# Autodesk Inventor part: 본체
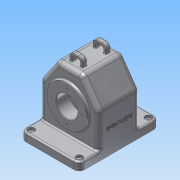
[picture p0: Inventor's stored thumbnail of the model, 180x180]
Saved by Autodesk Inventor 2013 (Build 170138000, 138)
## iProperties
Created: 2016-12
Part Number: 본체
Material: 알루미늄 6061
Document SubType Name: Modeling
Designer: Administrator
Density: 2.71 g/cm^3
Mass: 1063.78 g
Surface Area: 1146.71 cm^2
Volume: 392.539 cm^3
Author: Administrator
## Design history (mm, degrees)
sketch "스케치1"
  geometry: L1 (-65, 55)-(65, 55); L2 (75, 45)-(75, -45); L3 (65, -55)-(-65, -55); L4 (-75, -45)-(-75, 45); A1 r 10 centre (-65, 45) between (-65, 55) and (-75, 45); A2 r 10 centre (65, 45) between (75, 45) and (65, 55); A3 r 10 centre (-65, -45) between (-75, -45) and (-65, -55); A4 r 10 centre (65, -45) between (65, -55) and (75, -45); 6 further points
  constraints: 8 end point, 8 point on circle, 8 tangent, 6 point on line, 4 centre point, 3 equal radius, 2 midpoint, 2 parallel, 1 horizontal, 1 horizontal alignment, 1 perpendicular, 1 vertical alignment
  dimensions: "d0" = 150 distance of point (-75, 55) point (75, 55); "d2" = 110 distance of point (75, 55) point (75, -55); "d3" = 10 radius of A1
extrude "돌출1" new body sketch "스케치1" distance "d4" = 15; taper "d5" = 0 deg
sketch "스케치2"
  geometry: L1 (-55, 0)-(-55, 15) reference; L2 (-55, 15)-(55, 15) reference; L3 (55, 15)-(55, 0) reference; L4 (55, 0)-(-55, 0) reference; L5 (-55, 15)-(-55, 80); L6 (-23.491, 125)-(23.491, 125); L7 (55, 80)-(55, 15); L8 (-23.491, 125)-(-55, 80); L9 (23.491, 125)-(55, 80); 3 further points
  constraints: 10 end point, 2 midpoint, 2 perpendicular, 1 horizontal alignment, 1 point on line, 1 vertical, 1 vertical alignment
  dimensions: "d6" = 125 distance between parallel lines of L4 L6; "d7" = 80 distance from line of L7.start L4; "d24" = 35 deg angle of L5 L8; "d25" = 35 deg angle of L7 L9
extrude "돌출2" join sketch "스케치2" stored distance "d12" = 77; taper "d13" = 0 deg
sketch "스케치3"
  geometry: L1 (-15, -55)-(-15, 55) reference; L2 (-80, 55)-(-15, 55) reference; L3 (-15, -55)-(-80, -55) reference; L4 (0, -55)-(-15, -55) reference; L5 (0, 55)-(0, -55) reference; L6 (-15, 55)-(0, 55) reference; L7 (-125, -23.491)-(-125, 23.491) reference; L8 (-125, 23.491)-(-80, 55) reference; L9 (-80, -55)-(-125, -23.491) reference; C1 r 37.5 at (-65, 0); 2 further points
  constraints: 1 centre point, 1 horizontal alignment, 1 midpoint
  dimensions: "d15" = 65 distance from line of L5 C1.centre; "d16" = 75 diameter of C1
extrude "돌출3" join sketch "스케치3" distance "d17" = 5; taper "d18" = 0 deg
sketch "스케치4"
  geometry: L1 (15, 55)-(15, -55) reference; L2 (80, -55)-(15, -55) reference; L3 (15, 55)-(80, 55) reference; L4 (0, 55)-(15, 55) reference; L5 (0, -55)-(0, 55) reference; L6 (15, -55)-(0, -55) reference; L7 (125, 23.491)-(125, -23.491) reference; L8 (125, -23.491)-(80, -55) reference; L9 (80, 55)-(125, 23.491) reference; C1 r 31 at (65, 0); 2 further points
  constraints: 1 centre point, 1 horizontal alignment, 1 midpoint
  dimensions: "d19" = 62 diameter of C1; "d21" = 65 distance of point (0, 0) C1.centre
extrude "돌출4" join sketch "스케치4" distance "d22" = 10; taper "d23" = 0 deg
sketch "스케치6"
  geometry: L1 (-23.491, 125)-(23.491, 125) reference; L2 (23.491, 125)-(55, 80) reference; L3 (55, 80)-(55, 0) reference; L4 (55, 0)-(-55, 0) reference; L5 (-55, 0)-(-55, 80) reference; L6 (-55, 80)-(-23.491, 125) reference; L7 (50, 78.424)-(20.888, 120); L8 (20.888, 120)-(-20.888, 120); L9 (-20.888, 120)-(-50, 78.424); L10 (-50, 78.424)-(-50, 0); L11 (50, 0)-(50, 78.424); 1 further point
  constraints: 10 end point, 2 point on line, 2 other
  dimensions: "d26" = 5 distance between parallel lines of L1 L8; "d27" = 5 distance between parallel lines of L5 L10; "d28" = 5 distance between parallel lines of L11 L3
extrude "돌출5" cut sketch "스케치6" stored distance "d29" = 67; taper "d30" = 0 deg
sketch "스케치7"
  geometry: L1 (-33.5, 78.424)-(-33.5, 0) reference; L2 (-33.5, 120)-(-33.5, 78.424) reference; L3 (-43.5, 102.5)-(-43.5, 27.5) reference; L4 (33.5, 0)-(-33.5, 0) reference; L5 (-38.5, 65)-(-19.5, 65); L6 (-38.5, 111)-(-19.5, 92); L7 (-19.5, 92)-(-19.5, 65); L8 (-38.5, 125)-(-38.5, 80) reference; L9 (-38.5, 111)-(-38.5, 65); 2 further points
  constraints: 8 end point, 1 collinear, 1 horizontal alignment, 1 midpoint, 1 parallel, 1 perpendicular, 1 point on line
  dimensions: "d39" = 24 distance between parallel lines of L7 L3; "d40" = 54 diameter of L6.end L5; "d41" = 45 deg angle of L7 L6
revolve "회전1" sketch "스케치7" stored, may be unused: angle "d42" = 90 deg
hole "구멍1" diameter "d45" = 40; stored, may be unused: countersink angle "d49" = 90 deg, drill point angle "d51" = 0 deg; dims "d43" = 10, "d44" = 10, "d46" = 6, "d47" = 4, "d48" = 2, "d50" = 8
hole "구멍2" diameter "d54" = 5; stored, may be unused: countersink angle "d58" = 90 deg, drill point angle "d60" = 0 deg; dims "d52" = 10, "d53" = 10, "d55" = 6, "d56" = 12, "d57" = 5, "d59" = 8
hole "구멍3" diameter "d63" = 5; stored, may be unused: countersink angle "d67" = 90 deg, drill point angle "d69" = 0 deg; dims "d61" = 10, "d62" = 10, "d64" = 6, "d65" = 12, "d66" = 5, "d68" = 8
hole "구멍4" diameter "d72" = 5; stored, may be unused: countersink angle "d76" = 90 deg, drill point angle "d78" = 0 deg; dims "d70" = 10, "d71" = 10, "d73" = 6, "d74" = 12, "d75" = 5, "d77" = 8
hole "구멍5" diameter "d81" = 5; stored, may be unused: countersink angle "d85" = 90 deg, drill point angle "d87" = 0 deg; dims "d79" = 10, "d80" = 10, "d82" = 6, "d83" = 12, "d84" = 5, "d86" = 8
node "작업 평면1"
sketch "스케치9"
  geometry: L1 (103.5, -15)-(103.5, -80) reference; L2 (130, 0)-(0, 0) reference; 3 further points
  constraints: 1 coincident, 1 other
  dimensions: "d102" = 38.5 distance from line of point (65, -45) L1; "d103" = 45 distance from line of L2 point (65, -45)
feature "엠보싱1" sketch "스케치9" dims "d6" = 125, "d7" = 80, "d24" = 35 deg, "d25" = 35 deg, "d104" = 0.5, "d105" = 0
chamfer "모따기1" distance "d106" = 1; stored, may be unused: second distance "d107" = 2, angle "d108" = 45 deg
chamfer "모따기2" distance "d109" = 1; stored, may be unused: second distance "d110" = 2, angle "d111" = 45 deg
fillet "모깎기3" dims "d113" = 10
fillet "모깎기4" dims "d114" = 10
fillet "모깎기5" dims "d115" = 8
sketch "스케치10" dims "d116" = 52
  geometry: C1 r 31 at (0, 0) reference; 3 further points
  constraints: 2 horizontal alignment, 1 coincident, 2 other
hole "구멍6" sketch "스케치10" at (26, 0) diameter "d118" = 2.459; stored, may be unused: countersink angle "d122" = 90 deg, drill point angle "d124" = 118 deg; dims "d119" = 6, "d120" = 12, "d121" = 5, "d123" = 8
sketch "스케치11" dims "d128" = 58
  geometry: C1 r 27 at (0, 0) reference; C2 r 41 at (0, 0) reference; 3 further points
  constraints: 2 horizontal alignment, 1 coincident, 2 other
hole "구멍7" sketch "스케치11" at (-29, 0) diameter "d130" = 2.459; stored, may be unused: countersink angle "d134" = 90 deg, drill point angle "d136" = 118 deg; dims "d131" = 6, "d132" = 12, "d133" = 5, "d135" = 8
fillet "모깎기6" dims "d140" = 3
fillet "모깎기7" dims "d141" = 3
fillet "모깎기8" dims "d142" = 3
fillet "모깎기9" dims "d143" = 3
fillet "모깎기11" dims "d145" = 5
fillet "모깎기12" dims "d146" = 3
fillet "모깎기13" dims "d147" = 3
fillet "모깎기14" dims "d148" = 3
node "작업 평면2"
sketch "스케치12"
  geometry: L1 (-76.847, 55)-(0, 55) reference; L2 (0, 55)-(0, 50) reference; L3 (0, 50)-(-77.478, 50) reference; L4 (-79.198, 49.457)-(-117.868, 22.381) reference; L5 (-120, 18.285)-(-120, -18.285) reference; L6 (-117.868, -22.381)-(-79.198, -49.457) reference; L7 (-77.478, -50)-(0, -50) reference; L8 (0, -50)-(0, -55) reference; L9 (0, -55)-(-76.847, -55) reference; L10 (-82.583, -53.192)-(-120.736, -26.477) reference; L11 (-125, -18.285)-(-125, 18.285) reference; L12 (-120.736, 26.477)-(-82.583, 53.192) reference; L13 (-125, -12.5)-(-132, -12.5); L14 (-140, -4.5)-(-140, 4.5); L15 (-132, 12.5)-(-125, 12.5); L16 (0, 47)-(0, -47) reference; L17 (-125, 7.5)-(-132, 7.5); L18 (-135, 4.5)-(-135, -4.5); L19 (-132, -7.5)-(-125, -7.5); C1 r 33.5 at (-65, 0) reference; C2 r 20 at (-65, 0) reference; A1 r 3 centre (-77.478, 47) between (-77.478, 50) and (-79.198, 49.457) reference; A2 r 5 centre (-115, 18.285) between (-117.868, 22.381) and (-120, 18.285) reference; A3 r 5 centre (-115, -18.285) between (-120, -18.285) and (-117.868, -22.381) reference; A4 r 3 centre (-77.478, -47) between (-79.198, -49.457) and (-77.478, -50) reference; A5 r 10 centre (-76.847, -45) between (-82.583, -53.192) and (-76.847, -55) reference; A6 r 10 centre (-115, -18.285) between (-125, -18.285) and (-120.736, -26.477) reference; A7 r 10 centre (-115, 18.285) between (-120.736, 26.477) and (-125, 18.285) reference; A8 r 10 centre (-76.847, 45) between (-76.847, 55) and (-82.583, 53.192) reference; A9 r 8 centre (-132, -4.5) between (-140, -4.5) and (-132, -12.5); A10 r 8 centre (-132, 4.5) between (-132, 12.5) and (-140, 4.5); A11 r 3 centre (-132, 4.5) between (-132, 7.5) and (-135, 4.5); A12 r 3 centre (-132, -4.5) between (-135, -4.5) and (-132, -7.5); 5 further points
  constraints: 12 end point, 8 point on circle, 8 point on line, 4 centre point, 4 tangent, 2 midpoint, 1 equal radius, 1 horizontal, 1 horizontal alignment, 1 perpendicular, 1 vertical, 4 other
  dimensions: "d150" = 25 distance of point (-140, -12.5) point (-140, 12.5); "d151" = 140 distance between parallel lines of L16 L14; "d152" = 8 radius of A9; "d153" = 5 distance between parallel lines of L14 L18; "d154" = 15 distance between parallel lines of L17 L19 (derived)
extrude "돌출7" join sketch "스케치12" distance "d155" = 8; taper "d156" = 0 deg
fillet "모깎기15" dims "d157" = 1
fillet "모깎기16" dims "d158" = 1
node "솔리드1"
pattern_circular "원형 패턴1" dims angle "d126" = 360 deg
pattern_circular "원형 패턴2" dims angle "d138" = 360 deg
mirror "대칭2"
node "투영된 루프1"
node "절단 모서리 투영1"
node "절단 모서리 투영2"
node "절단 모서리 투영3"
node "절단 모서리 투영4"
node "절단 모서리 투영6"
other parameters: "d88" = -10.5, "d149" = -12.5
